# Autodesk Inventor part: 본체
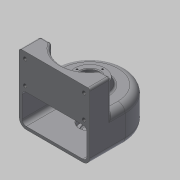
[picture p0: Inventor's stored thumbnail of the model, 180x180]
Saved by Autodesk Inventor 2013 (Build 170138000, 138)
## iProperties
Created: 2015-02
Part Number: 본체
Material: 일반
Document SubType Name: Modeling
Designer: Administrator
Density: 1 g/cm^3
Author: Administrator
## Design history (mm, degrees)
sketch "스케치1"
  geometry: L1 (-50, 0)-(-50, -50); L2 (-50, -50)-(50, -50); L3 (50, -50)-(50, 0); A1 r 50 centre (0, 0) between (50, 0) and (-50, 0); 1 further point
  constraints: 6 end point, 2 coincident, 2 point on circle, 2 tangent, 1 centre point, 1 parallel, 1 perpendicular, 1 vertical
  dimensions: "d0" = 100 diameter of A1; "d2" = 50 distance from line of point (0, 0) L2
extrude "돌출1" new body sketch "스케치1" stored distance "d3" = 50; taper "d4" = 0 deg
fillet "모깎기1" dims "d5" = 10
feature "쉘1" dims "d6" = 4
sketch "스케치2"
  geometry: L1 (0, 25)-(40, 25) reference; L2 (0, 21)-(40, 21) reference; L3 (40, -21)-(0, -21) reference; L4 (40, -25)-(0, -25) reference; L5 (0, -25)-(-50, -25) reference; L6 (0, -21)-(-50, -21) reference; L7 (-50, 25)-(0, 25) reference; L8 (-50, 21)-(0, 21) reference; L9 (0, 25)-(0, -25); L10 (0, -25)-(20, -25); L11 (20, -25)-(20, -33); L12 (20, -33)-(0, -33); L13 (0, -33)-(0, -25); L14 (25, 25)-(21.36, 35); L15 (21.36, 35)-(0, 35); L16 (0, 35)-(0, 25); L17 (25, 25)-(0, 25); 1 further point
  constraints: 18 end point, 4 perpendicular, 2 parallel, 1 collinear, 1 horizontal, 1 point on line
  dimensions: "d7" = 40 diameter of L11 L9; "d9" = 8 distance of L10.end L11.end; "d10" = 50 diameter of L14.start L9; "d11" = 110 deg angle of L1 L14; "d12" = 10 distance between parallel lines of L1 L15
revolve "회전1" sketch "스케치2" stored, may be unused: angle "d13" = 90 deg
sketch "스케치3"
  geometry: L1 (40, -21)-(0, -21) reference; L2 (-20, -33)-(20, -33) reference; L3 (20, -25)-(-20, -25) reference; L4 (0, -21)-(-50, -21) reference; L5 (0, -33)-(0, -21); L6 (0, -21)-(14, -21); L7 (14, -21)-(14, -29); L8 (14, -29)-(10, -29); L9 (0, -29)-(0, -21); L10 (0, -31)-(8, -31); A1 r 2 centre (8, -29) between (8, -31) and (10, -29); 1 further point
  constraints: 12 end point, 3 perpendicular, 2 parallel, 2 point on circle, 2 point on line, 1 centre point, 1 horizontal, 1 midpoint, 1 tangent
  dimensions: "d14" = 28 diameter of L7 L5; "d16" = 8 distance of L6.end L7.end; "d17" = 2 distance between parallel lines of L8 L10; "d18" = 20 diameter of L8.end L5
revolve "회전2" sketch "스케치3" stored, may be unused: angle "d19" = 90 deg
hole "구멍1" diameter "d22" = 20; stored, may be unused: countersink angle "d26" = 90 deg, drill point angle "d28" = 0 deg; dims "d20" = 10, "d21" = 10, "d23" = 6, "d24" = 28, "d25" = 10, "d27" = 14
node "작업 평면1"
sketch "스케치4"
  geometry: L1 (-50, 0)-(-50, -50) reference; L2 (50, -50)-(50, 0) reference; L3 (-40, -50)-(40, -50) reference; L4 (-50, -20)-(-50, -50); L5 (-50, -50)-(50, -50); L6 (50, -50)-(50, -20); L7 (50, -20)-(34.641, -20); L8 (-50, -20)-(-34.641, -20); A1 r 40 centre (0, 0) between (-34.641, -20) and (34.641, -20); 1 further point
  constraints: 10 end point, 3 collinear, 2 point on circle, 2 point on line, 1 centre point, 1 coincident, 1 perpendicular
  dimensions: "d30" = 80 diameter of A1; "d31" = 30 distance between parallel lines of L5 L7
extrude "돌출2" join sketch "스케치4" stored distance "d32" = 50; taper "d33" = 0 deg
chamfer "모따기1" distance "d36" = 1; stored, may be unused: second distance "d37" = 2, angle "d38" = 45 deg
fillet "모깎기3" dims "d50" = 3, "d51" = 0.3
sketch "스케치6"
  geometry: C1 r 21.36 at (0, 0) reference; 1 further point
  constraints: 1 vertical alignment
  dimensions: "d52" = 18 distance of C1.centre point (0, 18)
hole "구멍3" sketch "스케치6" at (0, 18) diameter "d53" = 2.459; stored, may be unused: countersink angle "d57" = 90 deg, drill point angle "d59" = 118 deg; dims "d54" = 6, "d55" = 28, "d56" = 10, "d58" = 9
node "작업 평면2"
sketch "스케치7"
  geometry: L1 (40, -25)-(-40, -25) reference; 2 further points
  constraints: 1 coincident, 1 other
  dimensions: "d64" = 25 distance from line of L1 point (0, 0)
feature "엠보싱1" sketch "스케치7" dims "d0" = 100, "d2" = 50, "d65" = 0.5, "d66" = 0
sketch "스케치8"
  geometry: L1 (-7, 95)-(87, 95) reference; L2 (80, 0)-(0, 0) reference; L3 (40, 95)-(40, 0); 5 further points
  constraints: 2 end point, 2 horizontal alignment, 2 midpoint, 2 vertical alignment, 1 symmetric about line
  dimensions: "d68" = 33 distance of point (81.75, 86) point (81.75, 53); "d70" = 9 distance from line of L1 point (81.75, 86); "d71" = 83.5 distance of point (-1.75, 86) point (81.75, 86)
hole "구멍4" sketch "스케치8" at (-1.75, 86), (81.75, 86), (81.75, 53), (-1.75, 53) diameter "d72" = 5.134; stored, may be unused: countersink angle "d76" = 90 deg, drill point angle "d78" = 118 deg; dims "d73" = 10, "d74" = 28, "d75" = 10, "d77" = 13
node "솔리드1"
pattern_circular "원형 패턴2" dims angle "d61" = 360 deg
node "투영된 루프1"
other parameters: "d29" = -95
